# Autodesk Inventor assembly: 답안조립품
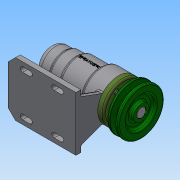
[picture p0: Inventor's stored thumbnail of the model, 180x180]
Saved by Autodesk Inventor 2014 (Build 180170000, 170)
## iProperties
Created: 2017-09
Part Number: 답안조립품
Document SubType Name: Assembly
Designer: NET
Author: NET
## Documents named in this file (11)
- C:\Users\NET\Desktop\470907V1009\답안조립품.iam
- C:\Users\NET\Desktop\470907V1009\본체.ipt
- C:\Users\NET\Desktop\470907V1009\축.ipt
- C:\Users\NET\Desktop\470907V1009\베어링 6004.ipt
- C:\Users\NET\Desktop\470907V1009\어댑터슬리브.ipt
- C:\Users\NET\Desktop\470907V1009\볼트 M4 x 12.ipt
- C:\Users\NET\Desktop\470907V1009\베어링 51202.ipt
- C:\Users\NET\Desktop\470907V1009\커버.ipt
- C:\Users\NET\Desktop\470907V1009\키 5 x 5 x 16.ipt
- C:\Users\NET\Desktop\470907V1009\V벨트풀리.ipt
- C:\Users\NET\Desktop\470907V1009\멈춤나사 M3x8.ipt
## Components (1 placed, 1 different names)
1. V벨트풀리:1
